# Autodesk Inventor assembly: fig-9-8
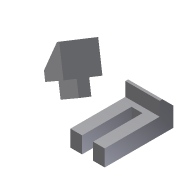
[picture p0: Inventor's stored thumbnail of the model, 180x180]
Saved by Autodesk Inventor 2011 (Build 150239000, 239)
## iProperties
Shininess: 64.0
Length Units: 11269
Angle Units: 11279
Time Units: 11290
Mass Units: 11283
Length Display Precision: 3
Angle Display Precision: 2
Created: 2002-01
Part Number: fig-9-8
Document SubType Name: Assembly
Designer: ***
Density: 0.0
Volumn: 0.0
Area: 0.0
PropertySet Name: Model Information
Control State: 0
Master: False
Checked Out: False
Author: ***
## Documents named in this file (3)
- C:\Users\CADSoft\Desktop\part files\c09-inv-2011-prt\fig-9-8.iam
- C:\Users\CADSoft\Desktop\inventor\c09-inv-2010-prt\c09\Part3.ipt
- C:\Users\CADSoft\Desktop\inventor\c09-inv-2010-prt\c09\Part4.ipt
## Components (2 placed, 2 different names)
1. Part3:1
2. Part4:1
